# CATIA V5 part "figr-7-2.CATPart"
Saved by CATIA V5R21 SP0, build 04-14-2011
Part number: Part1
Bounding box of the stored display mesh (mm): x -50 to 50, y -75 to 75, z 0 to 10
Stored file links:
  D:\CATIA V5R21 E-RESOURCES\CATIA-V5R21\catia-v5r21-prt\c07-catia-v5r20-prt\c07-catia-v5r21-figr-7-2.CATPart
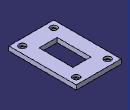
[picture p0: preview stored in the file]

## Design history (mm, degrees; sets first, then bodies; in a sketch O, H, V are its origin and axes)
Body1 (main body)
  Sketch1 on xy-plane, origin (0, 0, 0), H (1, 0, 0), V (0, 1, 0)
    line L1 (-50, 75) -> (50, 75)
    line L2 (50, 75) -> (50, -75)
    line L3 (50, -75) -> (-50, -75)
    line L4 (-50, -75) -> (-50, 75)
    axis line L5 (50, -75) -> (-50, 75)
    length L3 = 100
    length L2 = 150
    horizontal: L1 H, L3 H
    vertical: L2 V, L4 V
    midpoint: O L5
  Pad1: profile Sketch1, direction (0, 0, 1), length 10
  Sketch2 on face of Pad1, origin (0, 0, 10), H (1, 0, 0), V (0, 1, 0)
    line L1 (-20, 37.5) -> (20, 37.5)
    line L2 (20, 37.5) -> (20, -37.5)
    line L3 (20, -37.5) -> (-20, -37.5)
    line L4 (-20, -37.5) -> (-20, 37.5)
    axis line L5 (20, -37.5) -> (-20, 37.5)
    length L3 = 40
    length L2 = 75
    horizontal: L1 H, L3 H
    vertical: L2 V, L4 V
    midpoint: O L5
  Pocket1: profile Sketch2, direction (0, 0, -1), through (limit type 3)
  Sketch3 on face of Pad1, origin (-33.8832, 14.5619, 10), H (1, 0, 0), V (0, 1, 0)
    point P1 (68.8832, -74.5619)
    reference projected line E1 (-16.1168, -89.5619) -> (83.8832, -89.5619) from edge [face of Pad1 | face of Pad1]
    reference projected line E2 (83.8832, -89.5619) -> (83.8832, 60.4381) from edge [face of Pad1 | face of Pad1]
    distance P1 E1 = 15
    distance P1 E2 = 15
  Hole1: placed by Sketch3, at (35, -60, 10) direction (0, 0, -1), diameter 10, through (limit type 3), counterbore diameter 15, counterbore depth 5
  RectPattern1: of Hole1, direction 1 instances 2, spacing 70, along edge [face of Pad1 | face of Pad1] reversed, direction 2 instances 2, spacing 120, along edge [face of Pad1 | face of Pad1]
